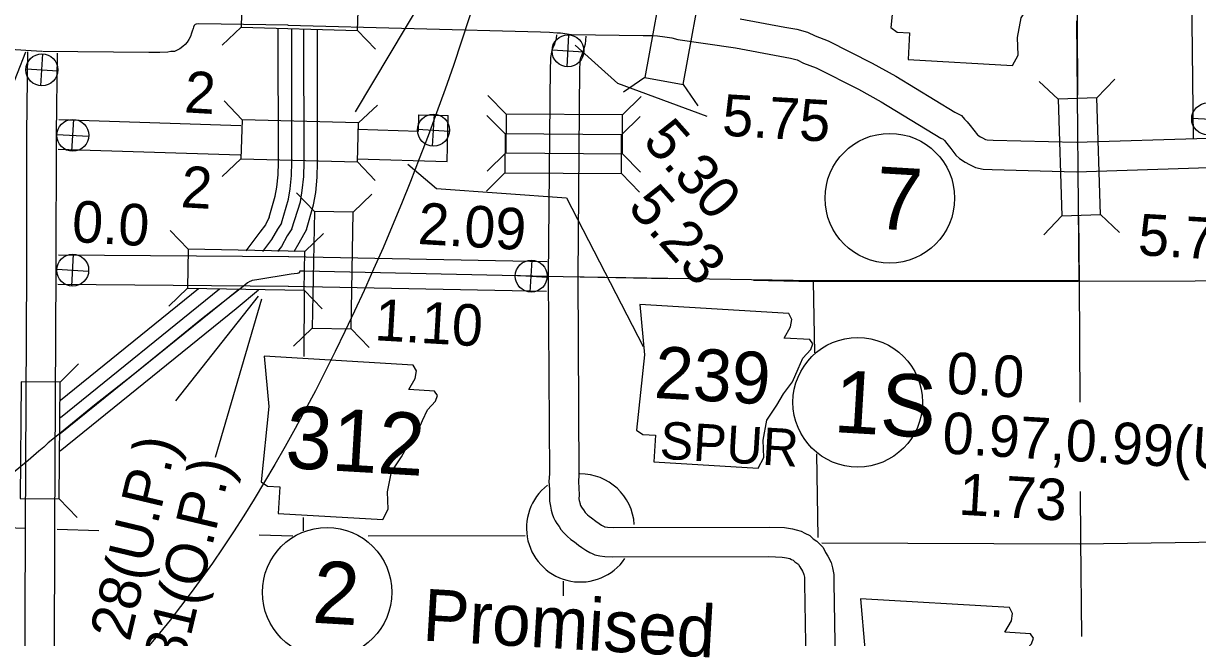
# Model space of a CAD drawing. Extents: x 1366406 to 1373462, y 376856 to 381998.
# Drawn here: x 1368242.9 to 1368436.7, y 380847.8 to 380949 of the extents above; entities that cross this region are included whole.
import ezdxf

# ---------------------------------------------------------------- set-up
doc = ezdxf.new("R2010")
doc.units = 0
for name, color, linetype in [('10', 7, 'Continuous'), ('19', 7, 'Continuous'), ('20', 7, 'Continuous'), ('21', 7, 'Continuous'), ('24', 7, 'Continuous'), ('25', 7, 'Continuous'), ('26', 7, 'Continuous'), ('27', 7, 'Continuous'), ('4', 7, 'Continuous'), ('5', 7, 'Continuous'), ('58', 7, 'Continuous'), ('6', 7, 'Continuous'), ('Default', 7, 'Continuous')]:
    doc.layers.add(name, color=color, linetype=linetype)

msp = doc.modelspace()

# ---------------------------------------------------------------- linework, layer by layer
at = {"layer": '10'}
msp.add_line((1368308.18, 380933.99), (1368313.04, 380933.86), dxfattribs=at)
for points in [[(1368436.05, 380930.06), (1368435.31, 380992.55)], [(1368361.24, 380949.83), (1368368.61, 380948.42), (1368370.59, 380948.09), (1368372.34, 380947.59), (1368373.61, 380946.98), (1368375.73, 380946.17), (1368382.99, 380942.49), (1368386.93, 380940.33), (1368396.67, 380934.41), (1368397.75, 380933.89), (1368398.27, 380933.29), (1368398.69, 380932.85), (1368399.16, 380932.21), (1368399.77, 380931.45), (1368400.37, 380930.68), (1368400.44, 380930.62), (1368400.86, 380930.33), (1368401.2, 380930.16), (1368401.69, 380929.93), (1368402, 380929.85), (1368402.95, 380929.82), (1368416.65, 380929.46), (1368438.43, 380930.14)], [(1368286.59, 380948.76), (1368271.86, 380948.96), (1368271.46, 380948.93), (1368271.42, 380948.93), (1368271.27, 380948.85), (1368271.14, 380948.78), (1368271.11, 380948.72), (1368270.99, 380948.41), (1368270.91, 380948.21), (1368270.78, 380947.77), (1368270.68, 380947.45), (1368270.47, 380946.91), (1368270.22, 380946.4), (1368269.93, 380945.97), (1368269.62, 380945.58), (1368269.21, 380945.23), (1368268.72, 380944.88), (1368267.85, 380944.43), (1368267.22, 380944.42), (1368266.76, 380944.3), (1368265.43, 380944.27), (1368263.61, 380944.25), (1368246.05, 380944.42)], [(1368286.56, 380948.76), (1368328.25, 380947.65), (1368329.73, 380947.59), (1368331, 380947.49), (1368331.58, 380947.47), (1368333.36, 380947.2), (1368345.18, 380947.05), (1368346.8, 380947.06), (1368347.59, 380946.99), (1368348.76, 380946.86), (1368349.92, 380946.65), (1368350.9, 380946.4), (1368360.44, 380945.03), (1368367.75, 380943.64), (1368369.52, 380943.34), (1368370.61, 380943.03), (1368371.69, 380942.51), (1368373.76, 380941.72), (1368380.72, 380938.19), (1368384.5, 380936.12), (1368394.35, 380930.13), (1368394.74, 380929.95), (1368394.96, 380929.72), (1368395.3, 380929.25), (1368395.96, 380928.43), (1368396.8, 380927.34), (1368397.44, 380926.78), (1368398.37, 380926.15), (1368399.06, 380925.79), (1368400.08, 380925.32), (1368401.32, 380925.02), (1368402.79, 380924.96), (1368416.67, 380924.6), (1368438.58, 380925.28)], [(1368330.88, 380947.16), (1368330.83, 380946.56), (1368330.77, 380946.36), (1368330.7, 380946.08), (1368330.49, 380945.49), (1368330.25, 380944.93), (1368330.09, 380944.32), (1368329.91, 380943.43), (1368329.9, 380942.68), (1368329.83, 380941.95), (1368329.55, 380907.31), (1368329.75, 380874.81), (1368329.65, 380873.52), (1368329.72, 380872.25), (1368329.77, 380871.22), (1368329.74, 380870.26), (1368329.9, 380869.45), (1368330.04, 380868.78), (1368330.18, 380868.2), (1368330.42, 380867.6), (1368330.68, 380867.06), (1368330.97, 380866.59), (1368331.32, 380866.13), (1368331.62, 380865.64), (1368332.03, 380865.13), (1368332.65, 380864.52), (1368333.24, 380863.98), (1368333.85, 380863.56), (1368334.55, 380863.05), (1368335.1, 380862.66), (1368335.74, 380862.2), (1368336.41, 380861.83), (1368336.76, 380861.68), (1368337.25, 380861.45), (1368338.07, 380861.26), (1368338.87, 380861.14), (1368340.17, 380861.09), (1368365.92, 380861.16), (1368368.14, 380861.07), (1368368.56, 380861.02), (1368368.88, 380860.97), (1368369.14, 380860.9), (1368369.44, 380860.81), (1368369.68, 380860.68), (1368369.97, 380860.54), (1368370.26, 380860.29), (1368370.74, 380859.95), (1368370.79, 380859.9), (1368370.87, 380859.82), (1368371.05, 380859.44), (1368371.48, 380858.77), (1368371.69, 380858.38), (1368371.73, 380858.21), (1368371.83, 380857.73), (1368371.83, 380856.79), (1368372.43, 380820.52)], [(1368335.74, 380946.95), (1368335.63, 380945.65), (1368335.46, 380945.07), (1368335.36, 380944.67), (1368335.01, 380943.71), (1368334.86, 380943.34), (1368334.82, 380943.2), (1368334.76, 380942.92), (1368334.76, 380942.42), (1368334.69, 380941.69), (1368334.41, 380907.3), (1368334.61, 380874.65), (1368334.52, 380873.46), (1368334.57, 380872.49), (1368334.63, 380871.27), (1368334.61, 380870.68), (1368334.66, 380870.42), (1368334.78, 380869.85), (1368334.82, 380869.69), (1368334.87, 380869.57), (1368334.95, 380869.4), (1368334.98, 380869.34), (1368335.34, 380868.88), (1368335.61, 380868.43), (1368335.65, 380868.39), (1368335.99, 380868.04), (1368336.27, 380867.79), (1368336.66, 380867.52), (1368337.37, 380867.01), (1368337.94, 380866.61), (1368338.33, 380866.32), (1368338.53, 380866.21), (1368338.79, 380866.1), (1368338.85, 380866.07), (1368338.96, 380866.05), (1368339.33, 380865.99), (1368340.26, 380865.95), (1368366.01, 380866.02), (1368368.55, 380865.92), (1368369.22, 380865.83), (1368369.87, 380865.74), (1368370.48, 380865.57), (1368371.3, 380865.33), (1368371.87, 380865.02), (1368372.71, 380864.63), (1368373.29, 380864.1), (1368373.89, 380863.68), (1368374.27, 380863.3), (1368374.92, 380862.63), (1368375.31, 380861.8), (1368375.68, 380861.23), (1368376.24, 380860.18), (1368376.47, 380859.31), (1368376.69, 380858.21), (1368376.69, 380856.84), (1368377.29, 380820.6)], [(1368245.96, 380944.42), (1368232.78, 380945.24)], [(1368243.61, 380944.34), (1368243.44, 380930.88)], [(1368248.47, 380944.13), (1368248.3, 380930.82)], [(1368248.76, 380933.19), (1368278.81, 380932.23)], [(1368297.92, 380926.75), (1368312.83, 380926.26), (1368313.04, 380933.86)], [(1368298.05, 380931.61), (1368308.11, 380931.28), (1368308.18, 380933.99)], [(1368243.44, 380930.85), (1368243.42, 380908.52)], [(1368248.3, 380930.85), (1368248.28, 380908.51)], [(1368248.64, 380928.33), (1368278.68, 380927.38)], [(1368248.72, 380910.92), (1368286.68, 380910.61)], [(1368286.71, 380910.61), (1368329.38, 380909.79)], [(1368243.42, 380908.53), (1368243.2, 380865.65), (1368243.06, 380822.93), (1368243.16, 380792.39)], [(1368248.28, 380908.5), (1368248.06, 380865.63), (1368247.92, 380822.93), (1368248.02, 380792.4)], [(1368248.6, 380906.06), (1368286.64, 380905.75)], [(1368286.62, 380905.75), (1368329.25, 380904.93)]]:
    msp.add_lwpolyline(points, dxfattribs=at)
at = {"layer": '19'}
for points in [[(1368284.99, 380926.13), (1368284.96, 380948.13)], [(1368287.22, 380926.17), (1368287.19, 380948.07)], [(1368289.25, 380926.15), (1368289.21, 380948.01)], [(1368291.47, 380926.13), (1368291.44, 380947.95)], [(1368283.47, 380917.13), (1368284.48, 380920.58), (1368284.72, 380922.07), (1368284.95, 380924.11), (1368284.99, 380926.13)], [(1368285.5, 380916.14), (1368286.66, 380920.08), (1368286.93, 380921.77), (1368287.17, 380923.97), (1368287.22, 380926.17)], [(1368287.19, 380915.16), (1368288.63, 380919.63), (1368288.94, 380921.5), (1368289.19, 380923.83), (1368289.25, 380926.15)], [(1368289.61, 380915.06), (1368290.81, 380919.13), (1368291.15, 380921.2), (1368291.42, 380923.69), (1368291.47, 380926.13)], [(1368283.47, 380917.13), (1368282.85, 380915.86), (1368281.92, 380914.62), (1368279.63, 380911.54)], [(1368285.5, 380916.14), (1368284.85, 380915.12), (1368283.87, 380913.42), (1368282.35, 380911.47)], [(1368287.19, 380915.16), (1368286.47, 380914.02), (1368285.49, 380912.29), (1368284.86, 380911.45)], [(1368289.61, 380915.06), (1368288.35, 380912.82), (1368287.53, 380911.37)], [(1368271.79, 380905.27), (1368249.04, 380886.89)], [(1368281.72, 380905.09), (1368278.05, 380901.99), (1368248.98, 380878.51)], [(1368278.4, 380905.15), (1368249, 380881.39)], [(1368275.25, 380905.21), (1368249.02, 380884.01)]]:
    msp.add_lwpolyline(points, dxfattribs=at)
at = {"layer": '20'}
for p, q in [((1368278.84, 380948.41), (1368275.74, 380945.46)), ((1368298.08, 380947.89), (1368301.02, 380944.78)), ((1368345.47, 380940.15), (1368341.95, 380937.72)), ((1368351.78, 380939), (1368354.21, 380935.48)), ((1368413.69, 380936.57), (1368410.57, 380939.49)), ((1368420.1, 380936.77), (1368423.03, 380939.88)), ((1368278.99, 380933.16), (1368276.04, 380936.27)), ((1368322.57, 380934.1), (1368319.56, 380937.14)), ((1368322.57, 380934.1), (1368319.56, 380937.14)), ((1368341.81, 380933.98), (1368344.85, 380936.99)), ((1368341.81, 380933.98), (1368344.85, 380936.99)), ((1368298.23, 380932.64), (1368301.33, 380935.59)), ((1368322.4, 380930.82), (1368319.4, 380933.86)), ((1368341.65, 380930.7), (1368344.69, 380933.71)), ((1368322.58, 380930.86), (1368322.4, 380930.86)), ((1368322.58, 380930.86), (1368322.4, 380930.86)), ((1368278.81, 380926.75), (1368275.71, 380923.81)), ((1368322.53, 380927.69), (1368319.48, 380924.68)), ((1368322.53, 380927.69), (1368319.48, 380924.68)), ((1368341.77, 380927.57), (1368344.78, 380924.52)), ((1368341.77, 380927.57), (1368344.78, 380924.52)), ((1368298.05, 380926.23), (1368300.99, 380923.13)), ((1368322.36, 380924.41), (1368319.32, 380921.4)), ((1368341.61, 380924.29), (1368344.61, 380921.24)), ((1368290.93, 380918.06), (1368287.96, 380921.14)), ((1368297.35, 380917.94), (1368300.43, 380920.91)), ((1368414.29, 380917.33), (1368411.36, 380914.21)), ((1368420.7, 380917.53), (1368423.82, 380914.6)), ((1368270.13, 380911.81), (1368267.16, 380914.89)), ((1368289.37, 380911.46), (1368292.45, 380914.43)), ((1368270.01, 380905.4), (1368266.94, 380902.43)), ((1368289.26, 380905.05), (1368292.23, 380901.97)), ((1368290.58, 380898.82), (1368287.51, 380895.85)), ((1368297, 380898.7), (1368299.97, 380895.62)), ((1368248.95, 380889.9), (1368252, 380892.9)), ((1368248.8, 380870.66), (1368251.8, 380867.61))]:
    msp.add_line(p, q, dxfattribs=at)
for points in [[(1368348.94, 380959.08), (1368345.47, 380940.15), (1368351.78, 380939), (1368355.25, 380957.93)], [(1368298.25, 380954.3), (1368279.01, 380954.82), (1368278.84, 380948.41), (1368298.08, 380947.89)], [(1368420.7, 380917.53), (1368420.1, 380936.77), (1368413.69, 380936.57), (1368414.29, 380917.33)], [(1368298.23, 380932.64), (1368278.99, 380933.16), (1368278.81, 380926.75), (1368298.05, 380926.23)], [(1368322.53, 380927.69), (1368341.77, 380927.57), (1368341.81, 380933.98), (1368322.57, 380934.1)], [(1368322.53, 380927.69), (1368341.77, 380927.57), (1368341.81, 380933.98), (1368322.57, 380934.1)], [(1368322.36, 380924.41), (1368341.61, 380924.29), (1368341.65, 380930.7), (1368322.4, 380930.82)], [(1368290.93, 380918.06), (1368290.58, 380898.82), (1368297, 380898.7), (1368297.35, 380917.94)], [(1368289.37, 380911.46), (1368270.13, 380911.81), (1368270.01, 380905.4), (1368289.26, 380905.05)], [(1368242.54, 380889.95), (1368242.39, 380870.7), (1368248.8, 380870.66), (1368248.95, 380889.9)]]:
    msp.add_lwpolyline(points, close=True, dxfattribs=at)
at = {"layer": '21'}
for points in [[(1368386.62, 380969.05), (1368387.37, 380960.77), (1368386.09, 380948.35), (1368387.14, 380947.6), (1368389.19, 380947.48), (1368388.94, 380943.1), (1368406.17, 380942.09), (1368407.1, 380943.82), (1368406.99, 380946.71), (1368407.6, 380949.97), (1368409.25, 380952.48), (1368410.33, 380954.34), (1368411.81, 380956.31), (1368412.76, 380958.45), (1368413.55, 380960.18), (1368414.87, 380961.62), (1368415.2, 380962.56), (1368414.7, 380963.27), (1368410.45, 380963.52), (1368411.52, 380965.38), (1368411.73, 380966.61), (1368411.22, 380967.59)], [(1368344.65, 380902.7), (1368345.4, 380894.42), (1368344.12, 380882), (1368345.17, 380881.26), (1368347.22, 380881.14), (1368346.96, 380876.76), (1368364.2, 380875.74), (1368365.13, 380877.47), (1368365.02, 380880.36), (1368365.62, 380883.62), (1368367.28, 380886.13), (1368368.35, 380887.99), (1368369.84, 380889.96), (1368370.79, 380892.1), (1368371.58, 380893.84), (1368372.9, 380895.27), (1368373.23, 380896.21), (1368372.72, 380896.93), (1368368.48, 380897.18), (1368369.55, 380899.04), (1368369.76, 380900.26), (1368369.25, 380901.24)], [(1368282.66, 380894.19), (1368283.41, 380885.91), (1368282.13, 380873.5), (1368283.18, 380872.75), (1368285.23, 380872.63), (1368284.98, 380868.25), (1368302.21, 380867.24), (1368303.14, 380868.97), (1368303.03, 380871.85), (1368303.64, 380875.11), (1368305.3, 380877.62), (1368306.37, 380879.48), (1368307.85, 380881.45), (1368308.8, 380883.59), (1368309.59, 380885.33), (1368310.91, 380886.76), (1368311.24, 380887.71), (1368310.74, 380888.42), (1368306.5, 380888.67), (1368307.57, 380890.53), (1368307.78, 380891.75), (1368307.26, 380892.73)], [(1368381.07, 380854.21), (1368381.82, 380845.93), (1368380.54, 380833.51), (1368381.59, 380832.77), (1368383.65, 380832.65), (1368383.39, 380828.27), (1368400.62, 380827.25), (1368401.55, 380828.98), (1368401.45, 380831.87), (1368402.05, 380835.13), (1368403.71, 380837.64), (1368404.78, 380839.5), (1368406.27, 380841.47), (1368407.22, 380843.61), (1368408, 380845.35), (1368409.32, 380846.78), (1368409.65, 380847.72), (1368409.15, 380848.44), (1368404.91, 380848.69), (1368405.98, 380850.55), (1368406.19, 380851.77), (1368405.67, 380852.75)]]:
    msp.add_lwpolyline(points, close=True, dxfattribs=at)
msp.add_lwpolyline([(1368306.36, 380925.82), (1368311.08, 380921.83), (1368332.55, 380920.31), (1368345.22, 380895.79)], dxfattribs=at)
at = {"layer": '24'}
for start, end in [(3.7545, 90.5477), (127.7415, 325.5321)]:
    msp.add_arc((1368334.85, 380865.87), 8.91, start, end, dxfattribs=at)
at = {"layer": '25'}
msp.add_line((1368243.23, 380944.32), (1368239.13, 380933.77), dxfattribs=at)
msp.add_lwpolyline([(1368355.75, 380933.7), (1368341.02, 380939.16), (1368333.99, 380945.44)], dxfattribs=at)
at = {"layer": '26'}
for p, q in [((1368332.64, 380941.91), (1368332.95, 380947.16)), ((1368245.81, 380938.78), (1368246.12, 380944.03)), ((1368330.16, 380944.69), (1368335.42, 380944.38)), ((1368243.34, 380941.56), (1368248.59, 380941.25)), ((1368250.91, 380927.97), (1368251.22, 380933.22)), ((1368310.45, 380928.83), (1368310.76, 380934.09)), ((1368435.74, 380933.45), (1368440.99, 380933.14)), ((1368248.44, 380930.75), (1368253.69, 380930.44)), ((1368307.98, 380931.62), (1368313.23, 380931.31)), ((1368250.9, 380905.74), (1368251.2, 380911)), ((1368326.57, 380904.76), (1368326.88, 380910.02)), ((1368248.42, 380908.52), (1368253.68, 380908.21)), ((1368324.1, 380907.54), (1368329.35, 380907.23))]:
    msp.add_line(p, q, dxfattribs=at)
for centre in [(1368332.79, 380944.53), (1368245.96, 380941.4), (1368438.37, 380933.3), (1368251.07, 380930.6), (1368310.6, 380931.46), (1368251.05, 380908.37), (1368326.73, 380907.39)]:
    msp.add_circle(centre, 2.63, dxfattribs=at)
at = {"layer": '27'}
for centre in [(1368385.92, 380920.23), (1368380.62, 380886.59), (1368293.04, 380855.26)]:
    msp.add_circle(centre, 10.69, dxfattribs=at)
at = {"layer": '4'}
msp.add_lwpolyline([(1368332.02, 380857.11), (1368332, 380854.69)], dxfattribs=at)
at = {"layer": '5'}
for points in [[(1368416.43, 380999.81), (1368416.63, 380992.79), (1368416.82, 380949.36), (1368416.92, 380937.23)], [(1368417.08, 380917.18), (1368417.16, 380906.53), (1368417.26, 380886.6)], [(1368334.81, 380907.28), (1368349.5, 380906.98)], [(1368363.39, 380906.7), (1368373.38, 380906.49), (1368416.98, 380906.58), (1368455.64, 380906.69)], [(1368373.27, 380906.49), (1368373.49, 380894.76)], [(1368289.26, 380904.94), (1368289.21, 380894.13)], [(1368373.79, 380878.11), (1368374.04, 380864.31)], [(1368417.33, 380871.89), (1368417.37, 380863.89), (1368417.58, 380847.97)], [(1368289.09, 380867.62), (1368289.08, 380865.41)], [(1368234.02, 380866.18), (1368243.2, 380865.82)], [(1368248.46, 380865.65), (1368255.36, 380865.46)], [(1368281.83, 380864.74), (1368287.4, 380864.59)], [(1368299.8, 380864.57), (1368325.72, 380864.61)], [(1368374.71, 380863.41), (1368417.3, 380863.26), (1368460.5, 380863.83), (1368478.94, 380863.55)]]:
    msp.add_lwpolyline(points, dxfattribs=at)
at = {"layer": '58'}
for p, q in [((1368314.21, 380962.2), (1368297.69, 380934.46)), ((1368268.05, 380886.83), (1368281.74, 380904.06)), ((1368274.64, 380877.52), (1368282.25, 380903.67))]:
    msp.add_line(p, q, dxfattribs=at)
at = {"layer": '6'}
for points in [[(1368416.72, 380949.5), (1368417.12, 380906.63), (1368373.41, 380906.6), (1368332.01, 380907.25), (1368289.25, 380908.2), (1368288.53, 380908.2), (1368288.5, 380908.06), (1368288.47, 380907.98), (1368288.44, 380907.93), (1368288.39, 380907.89), (1368288.33, 380907.87), (1368288.28, 380907.86), (1368288.08, 380907.83), (1368287.09, 380907.71), (1368281.45, 380906.78), (1368280.68, 380906.64), (1368280.46, 380906.58), (1368280.26, 380906.51), (1368279.91, 380906.26), (1368279.46, 380905.9), (1368272.28, 380900.3), (1368270.21, 380898.58), (1368265.98, 380895.13), (1368260.75, 380890.9), (1368254.67, 380886.09), (1368248.59, 380881.16)], [(1368248.59, 380881.16), (1368246.98, 380879.91), (1368246.26, 380879.21), (1368245.43, 380878.51), (1368243.7, 380876.97), (1368234.79, 380869.71)]]:
    msp.add_lwpolyline(points, dxfattribs=at)
at = {"layer": 'Default'}
msp.add_ellipse((1368265.23, 380986.62), major_axis=(44.98, 163.09), ratio=0.352669, dxfattribs=at)

# ---------------------------------------------------------------- texts
at = {"layer": '20'}
for p in [(1368269.35, 380934.4), (1368268.79, 380918.76)]:
    msp.add_text('2', height=6.84, rotation=356.6294, dxfattribs=at).set_placement(p)
at = {"layer": '21'}
for s, height, p in [('239', 8.554, (1368346.9, 380887.32)), ('312', 10.264, (1368285.98, 380875.8)), ('SPUR', 6.159, (1368347.84, 380877.3))]:
    msp.add_text(s, height=height, rotation=356.6294, dxfattribs=at).set_placement(p)
at = {"layer": '24'}
msp.add_text('Promised', height=8.554, rotation=356.6294, dxfattribs=at).set_placement((1368308.66, 380847.32))
at = {"layer": '25'}
for s, p in [('5.75', (1368358.13, 380930.57)), ('0.0', (1368250.79, 380913.05)), ('2.09', (1368307.91, 380912.7)), ('0.0', (1368395.17, 380888.06)), ('1.73', (1368397.16, 380868.08))]:
    msp.add_text(s, height=6.843, rotation=356.6294, dxfattribs=at).set_placement(p)
at = {"layer": '27'}
for s, height, p in [('7', 10.26, (1368383.32, 380915.24)), ('1S', 10.264, (1368376.5, 380881.69)), ('2', 10.26, (1368290.45, 380850.27))]:
    msp.add_text(s, height=height, rotation=356.6294, dxfattribs=at).set_placement(p)
at = {"layer": '58'}
for s, height, rotation, p in [('5.30', 6.843, 311.6294, (1368344.94, 380929.49)), ('5.23', 6.843, 311.6294, (1368342.46, 380918.65)), ('5.72', 6.843, 356.6294, (1368426.77, 380910.87)), ('1.10', 6.843, 356.6294, (1368300.76, 380896.83)), ('0.97,0.99(U.P.)', 6.8429, 356.6294, (1368394.47, 380878.18)), ('66.28(U.P.)', 6.8429, 76.6294, (1368257.51, 380834.61)), ('0.81(O.P.)', 6.843, 76.6294, (1368267.57, 380835.46))]:
    msp.add_text(s, height=height, rotation=rotation, dxfattribs=at).set_placement(p)

doc.saveas('drawing.dxf')
